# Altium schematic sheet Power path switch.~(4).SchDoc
size A3; SheetNumber: 5; SheetTotal: 6
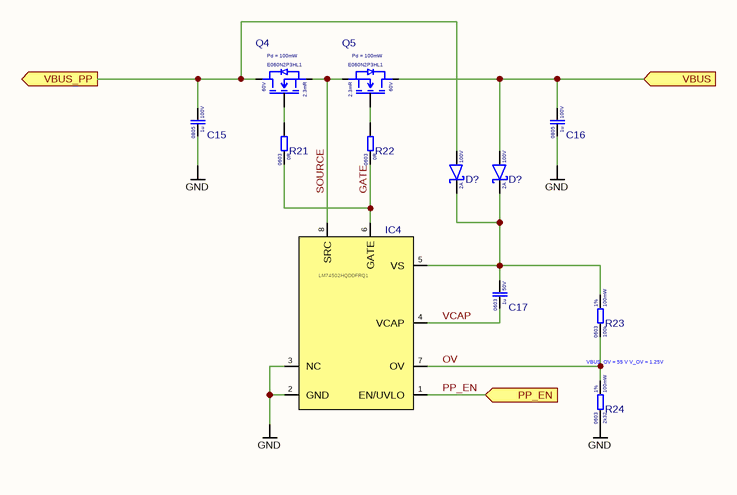
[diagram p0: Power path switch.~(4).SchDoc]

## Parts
(Parts that share a designator on the sheet are numbered #1, #2 ... from top to bottom, then left to right.)
C15  Voltage Rating: 100V  Case Code (Imperial): 0805  Capacitance: 1u  [Cap_0805]  (hidden comment: CC0805KKX7R0BB105)
C16  Voltage Rating: 100V  Case Code (Imperial): 0805  Capacitance: 1u  [Cap_0805]  (hidden comment: CC0805KKX7R0BB105)
C17  Voltage Rating: 50V  Case Code (Imperial): 0603  Capacitance: 1u  [CAP 0603]  (hidden comment: CL10A105KB8NNNC)
D?#1  Forward Current: 2A  Reverse Voltage: 100V  [SMAF]  (hidden comment: SS210F)
D?#2  Forward Current: 2A  Reverse Voltage: 100V  [SMAF]  (hidden comment: SS210F)
IC4  LM74502HQDDFRQ1  [SOT-23-8]
Q4  Pd = 100mW  Rds: 2.3mR  Voltage: 60V  [DFN-8 (5x6)]
Q5  Pd = 100mW  Rds: 2.3mR  Voltage: 60V  [DFN-8 (5x6)]
R21  Resistance: 0R  Case Code (Imperial): 0603  [RES_0603]  (hidden comment: 0603WAF0000T5E)
R22  Resistance: 0R  Case Code (Imperial): 0603  [RES_0603]  (hidden comment: 0603WAF0000T5E)
R23  Resistance Tolerance: 1%  Resistance: 100k  Power Rating: 100mW  Case Code (Imperial): 0603  [RES_0603]  (hidden comment: 0603WAF1003T5E)
R24  Resistance Tolerance: 1%  Resistance: 2k32  Power Rating: 100mW  Case Code (Imperial): 0603  [RES_0603]  (hidden comment: FRC0603F2321TS)

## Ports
PP_EN (in, see CHARGER[5A], USB PD[3A]), VBUS (in, see CHARGER[6A], USB protection[5A]), VBUS_PP (out, see CHARGER[5A])

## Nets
GND: C15.1 C16.1 IC4.2(GND) IC4.3(NC) R24.1
GATE: IC4.6(GATE) R21.1 R22.1
OV: IC4.7(OV) R23.1 R24.2
PP_EN: IC4.1(EN/UVLO) ; port PP_EN
SOURCE: IC4.8(SRC) Q4.S Q5.S
VBUS: C16.2 D?#2.A Q5.D ; port VBUS
VBUS_PP: C15.2 D?#1.A Q4.D ; port VBUS_PP
VCAP: C17.1 IC4.4(VCAP)
NetC17_2: C17.2 D?#1.K D?#2.K IC4.5(VS) R23.2
NetQ4_G: Q4.G R21.2
NetQ5_G: Q5.G R22.2

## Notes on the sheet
- VBUS_OV = 55 V V_OV = 1.25V

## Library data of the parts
C15 C16 = CC0805KKX7R0BB105: Cap 1uF 100V 0805 X7R; Manufacturer: Yageo
C17 = CL10A105KB8NNNC: Cap 1uF 50V 0603 X5R; Manufacturer: Samsung
D?#1 D?#2 = SS210F: Schottky 100V 2A 850mVf SMAF; Manufacturer: GOODWORK
IC4 = LM74502HQDDFRQ1: High-side switch controller IC 3.2~65V Reverse polarity protection; Manufacturer: Texas Instruments
Q4 Q5 = E060N2P3HL1: Nmos 60V 180A 2.3mR PDFN5x6-8; Manufacturer: Existar
R21 R22 = 0603WAF0000T5E: Res 0R 0603 1% 100mW 75V; Manufacturer: UNI-ROYAL
R23 = 0603WAF1003T5E: Res 100k 0603 1% 100mW 75V; Manufacturer: Uni-Royal
R24 = FRC0603F2321TS: Res 2k32 0603 1% 100mW 75V; Manufacturer: Uni-Royal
